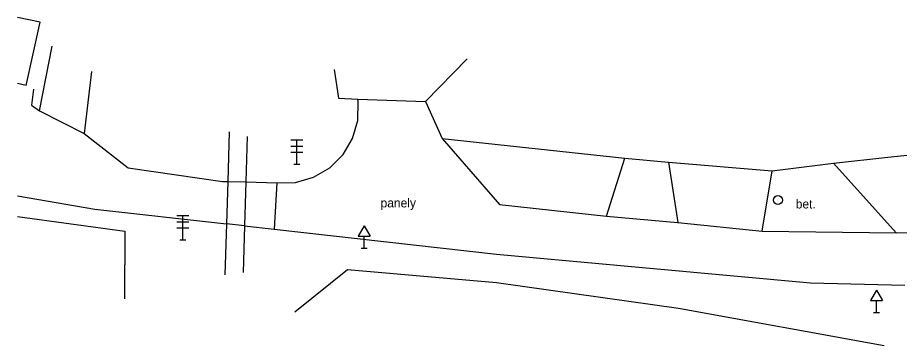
# Model space of a CAD drawing. Extents: x -762500 to -761246, y -1152986 to -1152252.
# Drawn here: x -762500 to -762426.4, y -1152944.6 to -1152917.3 of the extents above; entities that cross this region are included whole.
import ezdxf

# ---------------------------------------------------------------- set-up
doc = ezdxf.new("R2010")
doc.units = 0
for name, color, linetype in [('Vrstva 1', 7, 'Continuous'), ('Vrstva 10', 7, 'Continuous'), ('Vrstva 11', 7, 'Continuous'), ('Vrstva 14', 7, 'Continuous'), ('Vrstva 4', 7, 'Continuous'), ('Vrstva 9', 7, 'Continuous')]:
    doc.layers.add(name, color=color, linetype=linetype)

msp = doc.modelspace()

# ---------------------------------------------------------------- linework, layer by layer
at = {"layer": 'Vrstva 1'}
for radius in [0.375, 0.0005]:
    msp.add_circle((-762436.55, -1152932.521), radius, dxfattribs=at)
at = {"layer": 'Vrstva 10'}
for p, q in [((-762498.17, -1152925.07), (-762497.13, -1152919.68)), ((-762493.83, -1152921.8), (-762494.44, -1152926.96)), ((-762498.68, -1152923.28), (-762498.84, -1152924.6)), ((-762498.84, -1152924.6), (-762498.17, -1152925.07)), ((-762498.17, -1152925.07), (-762494.44, -1152926.96)), ((-762494.44, -1152926.96), (-762490.78, -1152929.82)), ((-762464.56, -1152927.39), (-762459.79, -1152932.89)), ((-762450.84, -1152933.85), (-762449.33, -1152929.03)), ((-762445.69, -1152929.36), (-762444.91, -1152934.38)), ((-762490.78, -1152929.82), (-762482.9, -1152930.97)), ((-762437.86, -1152935.1), (-762437.02, -1152930.07)), ((-762431.92, -1152929.45), (-762426.67, -1152935.25)), ((-762482.9, -1152930.97), (-762482.47, -1152930.98)), ((-762482.47, -1152930.98), (-762480.95, -1152931.01)), ((-762480.95, -1152931.01), (-762478.37, -1152931.07)), ((-762478.37, -1152931.07), (-762478.58, -1152934.96)), ((-762500, -1152932.16), (-762493.55, -1152933.29)), ((-762459.79, -1152932.89), (-762450.84, -1152933.85)), ((-762493.55, -1152933.29), (-762482.58, -1152934.51)), ((-762481.06, -1152934.68), (-762482.58, -1152934.51)), ((-762450.84, -1152933.85), (-762444.91, -1152934.38)), ((-762444.91, -1152934.38), (-762437.86, -1152935.1)), ((-762481.06, -1152934.68), (-762478.58, -1152934.96)), ((-762478.58, -1152934.96), (-762460.04, -1152937.03)), ((-762437.86, -1152935.1), (-762426.67, -1152935.25)), ((-762426.67, -1152935.25), (-762419.69, -1152935.07)), ((-762460.04, -1152937.03), (-762433.84, -1152939.42)), ((-762433.84, -1152939.42), (-762425.95, -1152939.61))]:
    msp.add_line(p, q, dxfattribs=at)
msp.add_lwpolyline([(-762478.37, -1152931.07), (-762476.8, -1152931.04), (-762475.3, -1152930.62), (-762473.95, -1152929.83), (-762472.84, -1152928.72), (-762472.04, -1152927.38), (-762471.62, -1152925.87), (-762471.58, -1152924.3), (-762471.61, -1152924.1)], dxfattribs=at)
at = {"layer": 'Vrstva 11'}
for points in [[(-762500, -1152933.89), (-762491.04, -1152935.12), (-762491.09, -1152940.75)], [(-762476.87, -1152941.84), (-762472.46, -1152938.3), (-762460.03, -1152939.39), (-762444.83, -1152941.55), (-762427.67, -1152944.64)]]:
    msp.add_lwpolyline(points, dxfattribs=at)
at = {"layer": 'Vrstva 4'}
for p, q in [((-762498.11, -1152917.68), (-762500, -1152917.3)), ((-762499.29, -1152922.96), (-762498.11, -1152917.68)), ((-762499.29, -1152922.96), (-762500, -1152922.8))]:
    msp.add_line(p, q, dxfattribs=at)
at = {"layer": 'Vrstva 9'}
for p, q in [((-762465.97, -1152924.3), (-762462.48, -1152920.73)), ((-762473.57, -1152921.64), (-762473.21, -1152924.02)), ((-762473.21, -1152924.02), (-762471.61, -1152924.1)), ((-762471.61, -1152924.1), (-762465.97, -1152924.3)), ((-762465.97, -1152924.3), (-762464.56, -1152927.39)), ((-762476.19, -1152927.53), (-762477.19, -1152927.53)), ((-762476.69, -1152929.53), (-762476.69, -1152927.53)), ((-762464.56, -1152927.39), (-762449.33, -1152929.03)), ((-762427.38, -1152928.93), (-762416.09, -1152927.76)), ((-762477.19, -1152928.03), (-762476.19, -1152928.03)), ((-762477.19, -1152928.53), (-762476.19, -1152928.53)), ((-762449.33, -1152929.03), (-762445.69, -1152929.36)), ((-762445.69, -1152929.36), (-762437.02, -1152930.07)), ((-762431.92, -1152929.45), (-762427.38, -1152928.93)), ((-762476.94, -1152929.53), (-762476.44, -1152929.53)), ((-762437.02, -1152930.07), (-762431.92, -1152929.45)), ((-762485.72, -1152933.84), (-762486.72, -1152933.84)), ((-762486.72, -1152934.34), (-762485.72, -1152934.34)), ((-762486.22, -1152935.84), (-762486.22, -1152933.84)), ((-762486.72, -1152934.84), (-762485.72, -1152934.84)), ((-762471.08, -1152934.674), (-762471.58, -1152935.54)), ((-762471.08, -1152934.674), (-762470.58, -1152935.54)), ((-762486.47, -1152935.84), (-762485.97, -1152935.84)), ((-762471.58, -1152935.54), (-762470.58, -1152935.54)), ((-762471.08, -1152936.54), (-762471.08, -1152935.54)), ((-762471.33, -1152936.54), (-762470.83, -1152936.54)), ((-762428.32, -1152940.044), (-762428.82, -1152940.91)), ((-762428.32, -1152940.044), (-762427.82, -1152940.91)), ((-762428.82, -1152940.91), (-762427.82, -1152940.91)), ((-762428.32, -1152941.91), (-762428.32, -1152940.91)), ((-762428.57, -1152941.91), (-762428.07, -1152941.91))]:
    msp.add_line(p, q, dxfattribs=at)
for points in [[(-762482.34, -1152926.82), (-762482.47, -1152930.98)], [(-762480.84, -1152927.22), (-762480.95, -1152931.01)], [(-762482.47, -1152930.98), (-762482.58, -1152934.51)], [(-762480.95, -1152931.01), (-762481.06, -1152934.68)], [(-762482.58, -1152934.51), (-762482.72, -1152938.76)], [(-762481.06, -1152934.68), (-762481.17, -1152938.55)]]:
    msp.add_lwpolyline(points, dxfattribs=at)

# ---------------------------------------------------------------- texts
at = {"layer": 'Vrstva 14'}
for s, p in [('panely', (-762469.71, -1152933.13)), ('bet.', (-762435.06, -1152933.22))]:
    msp.add_text(s, height=0.75, dxfattribs=at).set_placement(p)

doc.saveas('drawing.dxf')
